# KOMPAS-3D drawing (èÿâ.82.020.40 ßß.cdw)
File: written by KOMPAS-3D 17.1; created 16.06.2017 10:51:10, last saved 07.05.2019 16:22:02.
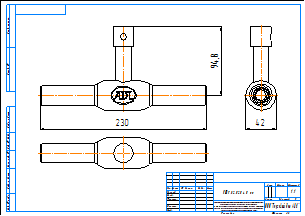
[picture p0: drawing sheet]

Sheet 1: A3, landscape

Title block, sheet 1: name: КШГ.82.020.40 сс; material: Внимание! Данный продукт является объектом авторского права ООО «Торговый Дом АДЛ». / Запрещается изменение, копирование, распространение / (в том числе путем копирования на другие сайты и ресурсы в Интернете) / или любое иное использование информации и объектов без предварительного / согласия правообладателя (ООО «Торговый Дом АДЛ»).; scale: 1:1; sheets: 1; organisation: ООО "Торговый дом АДЛ"; sheet format: A3; stored path: C:\Users\tra\Desktop\2д чертежи\Шаровые краны БИВАЛ\КШ_Бивал_серия_82_85\KOMPAS 2D\КШГ.82.020.40 сс.cdw

Views: Спереди 1, Проекционный вид 2, Проекционный вид 3
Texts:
  Klimkovich
  ADL
Dimensions and other numbers on the sheet: 230; 94,8; 42; 1:1; 1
